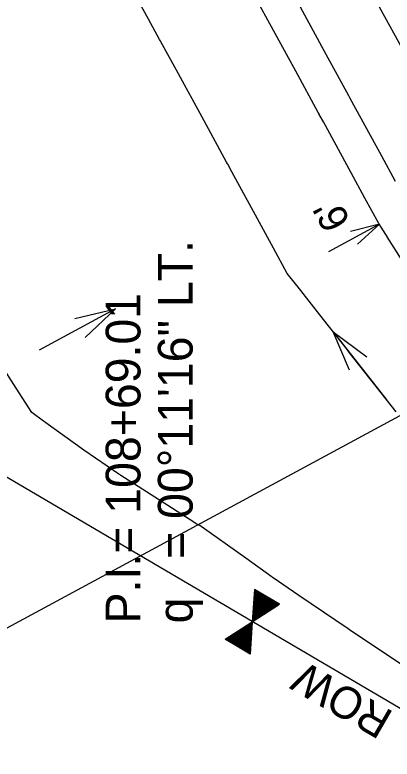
# Model space of a CAD drawing. Extents: x 1627557 to 1636561, y 783843 to 794002.
# Drawn here: x 1628143.1 to 1628208.2, y 784515.8 to 784644.3 of the extents above; entities that cross this region are included whole.
import ezdxf

# ---------------------------------------------------------------- set-up
doc = ezdxf.new("R2010")
doc.units = 0
for name, color, linetype in [('Dimensions', 7, 'Continuous'), ('Flow Arrows', 7, 'Continuous'), ('GATE', 7, 'Continuous'), ('R_Clearzone', 7, 'Continuous'), ('R_Ditch', 7, 'Continuous'), ('R_Horz Alg', 7, 'Continuous'), ('R_Horz Alg Annot', 7, 'Continuous'), ('R_Proposed Const Limits', 7, 'Continuous'), ('R_Proposed Road', 7, 'Continuous'), ('R_Proposed Shoulder', 7, 'Continuous'), ('R_ROW', 7, 'Continuous'), ('R_ROW Annot Labels', 7, 'Continuous')]:
    doc.layers.add(name, color=color, linetype=linetype)

msp = doc.modelspace()

# ---------------------------------------------------------------- linework, layer by layer
at = {"layer": 'Dimensions'}
for q in [(1628197.19, 784603.41), (1628200.98, 784606.9), (1628202.18, 784604.71)]:
    msp.add_line((1628205.97, 784608.19), q, dxfattribs=at)
at = {"layer": 'Flow Arrows'}
for p, q in [((1628160.43, 784593.56), (1628147.26, 784586.38)), ((1628198.02, 784589.57), (1628207.27, 784577.76))]:
    msp.add_line(p, q, dxfattribs=at)
for points in [[(1628153.43, 784591.87), (1628160.43, 784593.56), (1628155.21, 784588.59)], [(1628200.84, 784582.94), (1628198.02, 784589.57), (1628203.78, 784585.24)]]:
    msp.add_lwpolyline(points, dxfattribs=at)
at = {"layer": 'GATE'}
for p, q in [((1628184.35, 784544.05), (1628187.87, 784541.97)), ((1628184.36, 784544.16), (1628187.97, 784542.03)), ((1628184.37, 784544.38), (1628188.15, 784542.16)), ((1628184.37, 784544.27), (1628188.06, 784542.1)), ((1628184.38, 784544.49), (1628188.25, 784542.22)), ((1628184.39, 784544.6), (1628188.34, 784542.28)), ((1628184.4, 784544.83), (1628188.53, 784542.4)), ((1628184.4, 784544.72), (1628188.43, 784542.34)), ((1628184.41, 784544.94), (1628188.62, 784542.46)), ((1628184.42, 784545.05), (1628188.72, 784542.52)), ((1628184.26, 784542.71), (1628186.75, 784541.24)), ((1628184.27, 784542.93), (1628186.93, 784541.37)), ((1628184.27, 784542.82), (1628186.84, 784541.3)), ((1628184.28, 784543.04), (1628187.03, 784541.43)), ((1628184.29, 784543.15), (1628187.12, 784541.49)), ((1628184.3, 784543.27), (1628187.22, 784541.55)), ((1628184.31, 784543.49), (1628187.4, 784541.67)), ((1628184.31, 784543.38), (1628187.31, 784541.61)), ((1628184.32, 784543.6), (1628187.5, 784541.73)), ((1628184.33, 784543.71), (1628187.59, 784541.79)), ((1628184.34, 784543.94), (1628187.78, 784541.91)), ((1628184.34, 784543.82), (1628187.68, 784541.85)), ((1628184.17, 784541.48), (1628185.71, 784540.58)), ((1628184.18, 784541.59), (1628185.81, 784540.64)), ((1628184.19, 784541.7), (1628185.9, 784540.7)), ((1628184.2, 784541.82), (1628186, 784540.76)), ((1628184.21, 784542.04), (1628186.18, 784540.88)), ((1628184.21, 784541.93), (1628186.09, 784540.82)), ((1628184.22, 784542.15), (1628186.28, 784540.94)), ((1628184.23, 784542.26), (1628186.37, 784541)), ((1628184.24, 784542.49), (1628186.56, 784541.12)), ((1628184.24, 784542.37), (1628186.46, 784541.06)), ((1628184.25, 784542.6), (1628186.65, 784541.18)), ((1628184.08, 784540.14), (1628184.59, 784539.85)), ((1628184.09, 784540.25), (1628184.68, 784539.91)), ((1628184.1, 784540.37), (1628184.78, 784539.97)), ((1628184.11, 784540.59), (1628184.96, 784540.09)), ((1628184.11, 784540.48), (1628184.87, 784540.03)), ((1628184.12, 784540.7), (1628185.06, 784540.15)), ((1628184.13, 784540.81), (1628185.15, 784540.21)), ((1628184.14, 784541.04), (1628185.34, 784540.33)), ((1628184.14, 784540.92), (1628185.24, 784540.27)), ((1628184.15, 784541.15), (1628185.43, 784540.39)), ((1628184.16, 784541.26), (1628185.53, 784540.45)), ((1628184.17, 784541.37), (1628185.62, 784540.51)), ((1628183.07, 784538.86), (1628183.96, 784538.34)), ((1628183.17, 784538.93), (1628183.97, 784538.45)), ((1628183.26, 784538.99), (1628183.97, 784538.57)), ((1628183.35, 784539.05), (1628183.98, 784538.68)), ((1628183.45, 784539.11), (1628183.99, 784538.79)), ((1628183.54, 784539.17), (1628184, 784538.9)), ((1628183.64, 784539.23), (1628184.01, 784539.01)), ((1628183.73, 784539.29), (1628184.01, 784539.12)), ((1628183.82, 784539.35), (1628184.02, 784539.23)), ((1628183.92, 784539.41), (1628184.03, 784539.35)), ((1628184.01, 784539.47), (1628184.04, 784539.46)), ((1628184.04, 784539.59), (1628184.12, 784539.54)), ((1628184.05, 784539.7), (1628184.21, 784539.6)), ((1628184.06, 784539.81), (1628184.31, 784539.66)), ((1628184.07, 784539.92), (1628184.4, 784539.72)), ((1628184.08, 784540.03), (1628184.49, 784539.79)), ((1628181.1, 784537.59), (1628183.8, 784536)), ((1628181.2, 784537.65), (1628183.81, 784536.11)), ((1628181.29, 784537.71), (1628183.81, 784536.22)), ((1628181.38, 784537.77), (1628183.82, 784536.33)), ((1628181.48, 784537.83), (1628183.83, 784536.45)), ((1628181.57, 784537.89), (1628183.84, 784536.56)), ((1628181.67, 784537.95), (1628183.84, 784536.67)), ((1628181.76, 784538.01), (1628183.85, 784536.78)), ((1628181.85, 784538.07), (1628183.86, 784536.89)), ((1628181.95, 784538.13), (1628183.87, 784537)), ((1628182.04, 784538.2), (1628183.87, 784537.12)), ((1628182.13, 784538.26), (1628183.88, 784537.23)), ((1628182.23, 784538.32), (1628183.89, 784537.34)), ((1628182.32, 784538.38), (1628183.9, 784537.45)), ((1628182.42, 784538.44), (1628183.91, 784537.56)), ((1628182.51, 784538.5), (1628183.91, 784537.67)), ((1628182.6, 784538.56), (1628183.92, 784537.78)), ((1628182.7, 784538.62), (1628183.93, 784537.9)), ((1628182.79, 784538.68), (1628183.94, 784538.01)), ((1628182.89, 784538.74), (1628183.94, 784538.12)), ((1628182.98, 784538.8), (1628183.95, 784538.23)), ((1628179.41, 784536.49), (1628183.66, 784533.99)), ((1628179.51, 784536.55), (1628183.67, 784534.1)), ((1628179.6, 784536.62), (1628183.68, 784534.22)), ((1628179.7, 784536.68), (1628183.68, 784534.33)), ((1628179.79, 784536.74), (1628183.69, 784534.44)), ((1628179.88, 784536.8), (1628183.7, 784534.55)), ((1628179.98, 784536.86), (1628183.71, 784534.66)), ((1628180.07, 784536.92), (1628183.71, 784534.77)), ((1628180.16, 784536.98), (1628183.72, 784534.88)), ((1628180.26, 784537.04), (1628183.73, 784535)), ((1628180.35, 784537.1), (1628183.74, 784535.11)), ((1628180.45, 784537.16), (1628183.74, 784535.22)), ((1628180.54, 784537.22), (1628183.75, 784535.33)), ((1628180.63, 784537.28), (1628183.76, 784535.44)), ((1628180.73, 784537.34), (1628183.77, 784535.55)), ((1628180.82, 784537.41), (1628183.78, 784535.67)), ((1628180.91, 784537.47), (1628183.78, 784535.78)), ((1628181.01, 784537.53), (1628183.79, 784535.89))]:
    msp.add_line(p, q, dxfattribs=at)
for points in [[(1628184.42, 784545.07), (1628184.04, 784539.49), (1628188.73, 784542.53)], [(1628179.35, 784536.45), (1628184.04, 784539.49), (1628183.65, 784533.91)]]:
    msp.add_lwpolyline(points, close=True, dxfattribs=at)
at = {"layer": 'R_Clearzone'}
msp.add_lwpolyline([(1628208.88, 784575.74), (1628202.61, 784583.71), (1628200.66, 784586.2), (1628200.58, 784586.3), (1628200.45, 784586.47), (1628196.35, 784591.69), (1628191.79, 784597.49), (1628191.73, 784597.56), (1628191.5, 784597.86), (1628190.08, 784599.66), (1628187.69, 784604.05), (1628185.3, 784608.44), (1628180.51, 784617.22), (1628179.8, 784618.52), (1628179.76, 784618.6), (1628179.61, 784618.86), (1628175.72, 784626), (1628170.94, 784634.78), (1628168.26, 784639.68), (1628168.13, 784639.92), (1628168.06, 784640.05), (1628166.15, 784643.56), (1628161.83, 784651.48)], dxfattribs=at)
at = {"layer": 'R_Ditch'}
msp.add_lwpolyline([(1628208.88, 784575.74), (1628202.61, 784583.71), (1628200.66, 784586.2), (1628200.58, 784586.3), (1628200.45, 784586.47), (1628196.35, 784591.69), (1628191.79, 784597.49), (1628191.73, 784597.56), (1628191.5, 784597.86), (1628190.08, 784599.66), (1628187.69, 784604.05), (1628185.3, 784608.44), (1628180.51, 784617.22), (1628179.8, 784618.52), (1628179.76, 784618.6), (1628179.61, 784618.86), (1628175.72, 784626), (1628170.94, 784634.78), (1628168.26, 784639.68), (1628168.13, 784639.92), (1628168.06, 784640.05), (1628166.15, 784643.56), (1628161.83, 784651.48)], dxfattribs=at)
at = {"layer": 'R_Horz Alg'}
msp.add_line((1628236.53, 784589.68), (1627810.31, 785371.39), dxfattribs=at)
at = {"layer": 'R_Horz Alg Annot'}
msp.add_lwpolyline([(1628236.53, 784589.68), (1628073.18, 784501.32)], dxfattribs=at)
at = {"layer": 'R_Proposed Const Limits'}
msp.add_lwpolyline([(1628210.81, 784531.42), (1628201.4, 784537.7), (1628200.82, 784538.08), (1628200.8, 784538.1), (1628200.6, 784538.23), (1628192.08, 784544.02), (1628187.64, 784547.06), (1628187.51, 784547.15), (1628187.47, 784547.18), (1628182.92, 784550.44), (1628174.84, 784556.24), (1628174.78, 784556.28), (1628174.76, 784556.14), (1628174.72, 784556.17), (1628173.97, 784556.71), (1628164.37, 784562.86), (1628161.36, 784564.77), (1628161.23, 784564.85), (1628161.03, 784564.98), (1628154.95, 784569.11), (1628148.42, 784573.85), (1628148.34, 784573.91), (1628148.01, 784574.15), (1628145.99, 784575.62), (1628143.29, 784579.84), (1628140.59, 784584.07)], dxfattribs=at)
at = {"layer": 'R_Proposed Road'}
msp.add_lwpolyline([(1628208.76, 784615.54), (1628206.37, 784619.93), (1628201.58, 784628.71), (1628200.87, 784630.01), (1628200.83, 784630.09), (1628200.69, 784630.35), (1628196.79, 784637.49), (1628192.01, 784646.27)], dxfattribs=at)
at = {"layer": 'R_Proposed Shoulder'}
msp.add_lwpolyline([(1628211.22, 784599.8), (1628207.34, 784605.97), (1628207.29, 784606.05), (1628207.09, 784606.37), (1628205.89, 784608.28), (1628203.49, 784612.67), (1628201.1, 784617.06), (1628196.31, 784625.84), (1628195.61, 784627.13), (1628195.56, 784627.21), (1628195.42, 784627.48), (1628191.53, 784634.62), (1628186.74, 784643.4), (1628184.07, 784648.3)], dxfattribs=at)
at = {"layer": 'R_ROW'}
msp.add_line((1628234.18, 784509.96), (1628133.89, 784569.02), dxfattribs=at)

# ---------------------------------------------------------------- texts
at = {"layer": 'Dimensions'}
msp.add_text("6'", height=5, rotation=118.601, dxfattribs=at).set_placement((1628201.12, 784608.66))
at = {"layer": 'R_Horz Alg Annot'}
for s, p in [('q   = 00%%d11\'16" LT.', (1628173.75, 784539.19)), ('P.I.= 108+69.01', (1628164.75, 784539.19))]:
    msp.add_text(s, height=6, rotation=90, dxfattribs=at).set_placement(p)
at = {"layer": 'R_ROW Annot Labels'}
msp.add_text('PROP. ROW', height=5.5, rotation=149.9112, dxfattribs=at).set_placement((1628230.21, 784511.29))

doc.saveas('drawing.dxf')
